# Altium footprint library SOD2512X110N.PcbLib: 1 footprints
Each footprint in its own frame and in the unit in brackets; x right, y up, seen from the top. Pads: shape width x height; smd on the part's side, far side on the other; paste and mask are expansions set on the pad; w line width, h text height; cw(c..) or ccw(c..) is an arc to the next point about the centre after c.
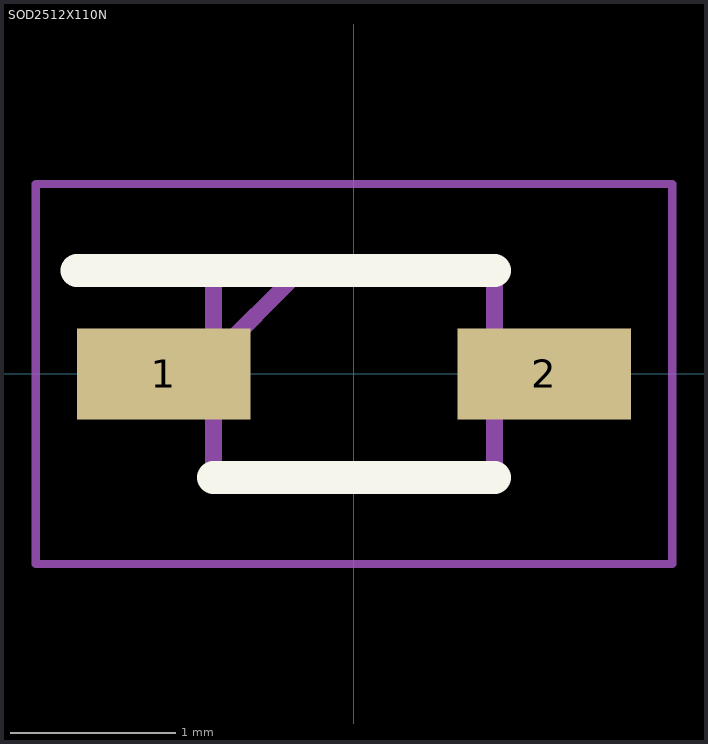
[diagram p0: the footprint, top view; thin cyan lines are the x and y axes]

## SOD2512X110N [mm]
pads (2):
  rect 1.05x0.55 smd: 1(-1.15,0) 2(1.15,0)
Top Overlay:
  lines w0.2: -1.675,0.625 0.85,0.625 ; -0.85,-0.625 0.85,-0.625
Mechanical 15:
  lines w0.1: -0.85,0.1 -0.325,0.625 ; -0.85,-0.625 0.85,-0.625 0.85,0.625 -0.85,0.625 -0.85,-0.625
Mechanical 20:
  lines w0.05: -1.925,-1.15 1.925,-1.15 1.925,1.15 -1.925,1.15 -1.925,-1.15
